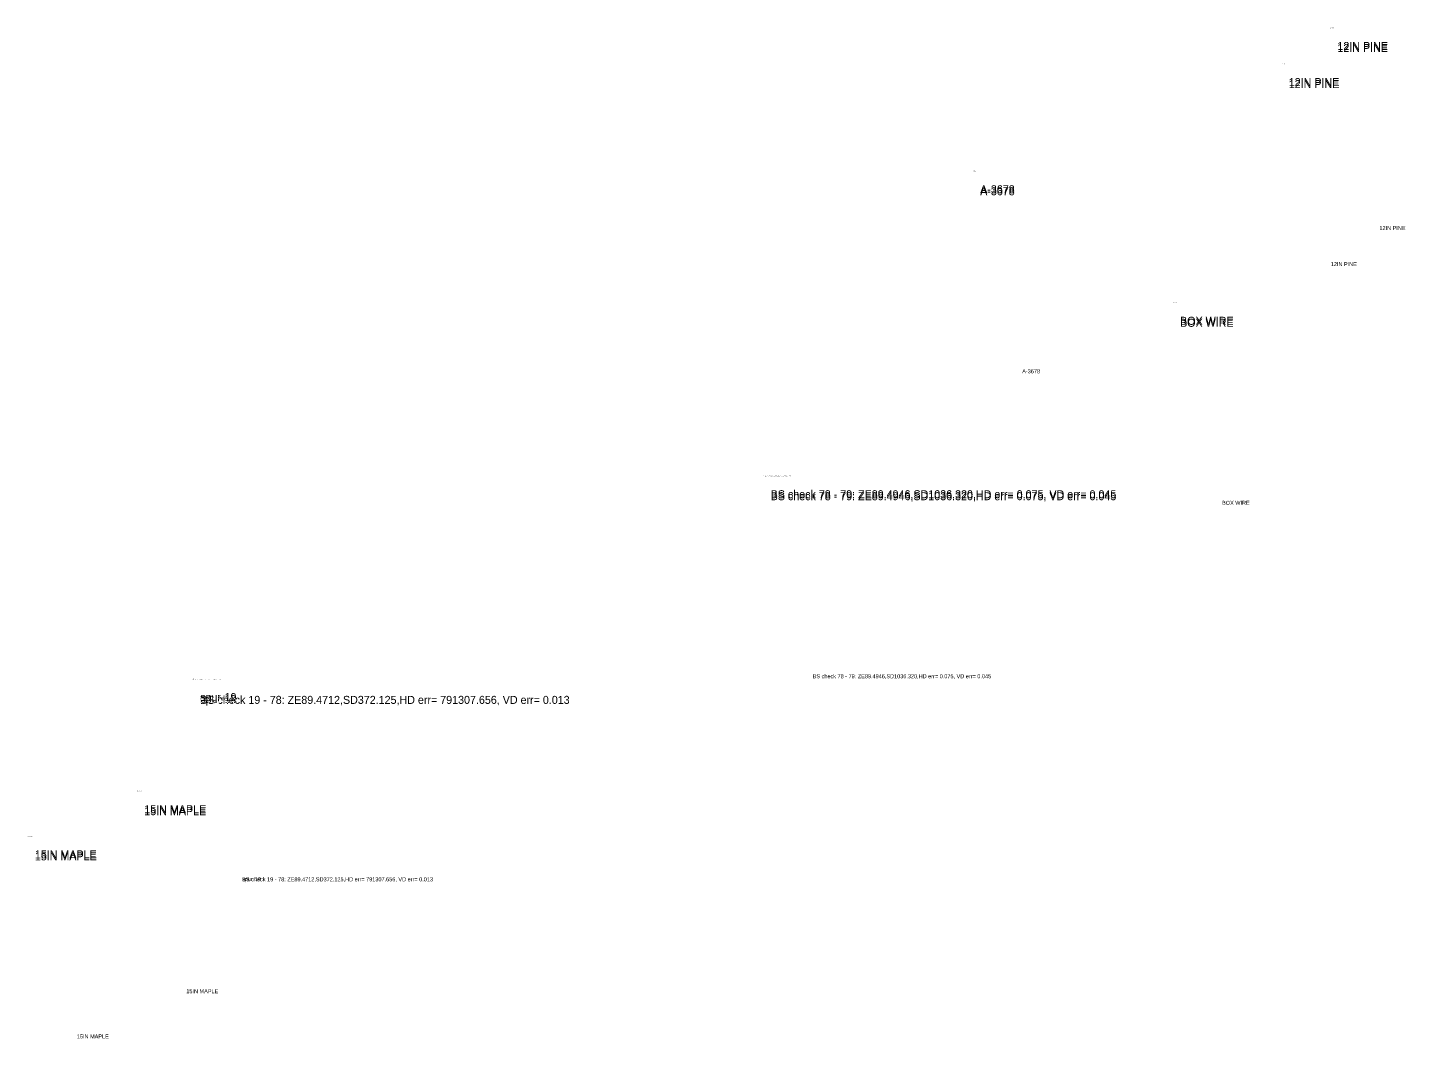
# Model space of a CAD drawing. Extents: x 5447 to 709667, y 4528 to 375472.
# Drawn here: x 704826 to 705377, y 374866 to 375270 of the extents above; entities that cross this region are included whole.
import ezdxf

# ---------------------------------------------------------------- set-up
doc = ezdxf.new("R2010")
doc.units = 0
doc.layers.add('SV_SURVEY_NOTES', color=7, linetype='Continuous')

msp = doc.modelspace()

# ---------------------------------------------------------------- texts
at = {"layer": 'SV_SURVEY_NOTES'}
for s, height, p in [('12IN PINE', 0.25, (705347.09, 375270.07)), ('12IN PINE', 3.2, (705350.04, 375261.35)), ('12IN PINE', 3.2, (705350.04, 375261.35)), ('12IN PINE', 3.2, (705350.04, 375261.35)), ('12IN PINE', 3.2, (705350.04, 375261.35)), ('12IN PINE', 3.2, (705350.04, 375261.35)), ('12IN PINE', 3.2, (705350.04, 375261.35)), ('12IN PINE', 3.2, (705350.04, 375261.35)), ('12IN PINE', 3.2, (705350.04, 375261.35)), ('12IN PINE', 3.2, (705350.04, 375260.55)), ('12IN PINE', 3.2, (705350.04, 375260.55)), ('12IN PINE', 3.2, (705350.04, 375260.55)), ('12IN PINE', 0.25, (705327.64, 375255.64)), ('12IN PINE', 3.2, (705330.59, 375246.91)), ('12IN PINE', 3.2, (705330.59, 375246.91)), ('12IN PINE', 3.2, (705330.59, 375246.91)), ('12IN PINE', 3.2, (705330.59, 375246.91)), ('12IN PINE', 3.2, (705330.59, 375246.91)), ('12IN PINE', 3.2, (705330.59, 375246.91)), ('12IN PINE', 3.2, (705330.59, 375246.91)), ('12IN PINE', 3.2, (705330.59, 375246.91)), ('12IN PINE', 3.2, (705330.59, 375246.11)), ('12IN PINE', 3.2, (705330.59, 375246.11)), ('12IN PINE', 3.2, (705330.59, 375246.11)), ('A-3678', 0.25, (705204.27, 375212.78)), ('A-3678', 0.25, (705204.27, 375212.78)), ('A-3678', 0.25, (705204.27, 375212.78)), ('A-3678', 0.25, (705204.27, 375212.78)), ('A-3678', 0.25, (705204.27, 375212.78)), ('A-3678', 0.25, (705204.27, 375212.78)), ('A-3678', 0.25, (705204.27, 375212.78)), ('A-3678', 0.25, (705204.27, 375212.78)), ('A-3678', 0.25, (705204.27, 375212.78)), ('A-3678', 3.2, (705207.22, 375204.05)), ('A-3678', 3.2, (705207.22, 375204.05)), ('A-3678', 3.2, (705207.22, 375204.05)), ('A-3678', 3.2, (705207.22, 375204.05)), ('A-3678', 3.2, (705207.22, 375204.05)), ('A-3678', 3.2, (705207.22, 375204.05)), ('A-3678', 3.2, (705207.22, 375204.05)), ('A-3678', 3.2, (705207.22, 375204.05)), ('A-3678', 3.2, (705207.22, 375204.05)), ('A-3678', 3.2, (705207.22, 375204.05)), ('A-3678', 3.2, (705207.22, 375204.05)), ('A-3678', 3.2, (705207.22, 375204.05)), ('A-3678', 3.2, (705207.22, 375204.05)), ('A-3678', 3.2, (705207.22, 375204.05)), ('A-3678', 3.2, (705207.22, 375204.05)), ('A-3678', 3.2, (705207.22, 375204.05)), ('A-3678', 3.2, (705207.22, 375204.05)), ('A-3678', 3.2, (705207.22, 375204.05)), ('A-3678', 3.2, (705207.22, 375204.05)), ('A-3678', 3.2, (705207.22, 375204.05)), ('A-3678', 3.2, (705207.22, 375204.05)), ('A-3678', 3.2, (705207.22, 375204.05)), ('A-3678', 3.2, (705207.22, 375204.05)), ('A-3678', 3.2, (705207.22, 375204.05)), ('A-3678', 3.2, (705207.22, 375204.05)), ('A-3678', 3.2, (705207.22, 375204.05)), ('A-3678', 3.2, (705207.22, 375204.05)), ('A-3678', 3.2, (705207.22, 375204.05)), ('A-3678', 3.2, (705207.22, 375204.05)), ('A-3678', 3.2, (705207.22, 375204.05)), ('A-3678', 3.2, (705207.22, 375204.05)), ('A-3678', 3.2, (705207.22, 375204.05)), ('A-3678', 3.2, (705207.22, 375204.05)), ('A-3678', 3.2, (705207.22, 375204.05)), ('A-3678', 3.2, (705207.22, 375204.05)), ('A-3678', 3.2, (705207.22, 375204.05)), ('A-3678', 3.2, (705207.22, 375204.05)), ('A-3678', 3.2, (705207.22, 375204.05)), ('A-3678', 3.2, (705207.22, 375204.05)), ('A-3678', 3.2, (705207.22, 375204.05)), ('A-3678', 3.2, (705207.22, 375204.05)), ('A-3678', 3.2, (705207.22, 375204.05)), ('A-3678', 3.2, (705207.22, 375204.05)), ('A-3678', 3.2, (705207.22, 375204.05)), ('A-3678', 3.2, (705207.22, 375204.05)), ('A-3678', 3.2, (705207.22, 375204.05)), ('A-3678', 3.2, (705207.22, 375204.05)), ('A-3678', 3.2, (705207.22, 375204.05)), ('A-3678', 3.2, (705207.22, 375204.05)), ('A-3678', 3.2, (705207.22, 375204.05)), ('A-3678', 3.2, (705207.22, 375204.05)), ('A-3678', 3.2, (705207.22, 375204.05)), ('A-3678', 3.2, (705207.22, 375204.05)), ('A-3678', 3.2, (705207.22, 375204.05)), ('A-3678', 3.2, (705207.22, 375204.05)), ('A-3678', 3.2, (705207.22, 375204.05)), ('A-3678', 3.2, (705207.22, 375204.05)), ('A-3678', 3.2, (705207.22, 375204.05)), ('A-3678', 3.2, (705207.22, 375204.05)), ('A-3678', 3.2, (705207.22, 375204.05)), ('A-3678', 3.2, (705207.22, 375204.05)), ('A-3678', 3.2, (705207.22, 375204.05)), ('A-3678', 3.2, (705207.22, 375204.05)), ('A-3678', 3.2, (705207.22, 375204.05)), ('A-3678', 3.2, (705207.22, 375204.05)), ('A-3678', 3.2, (705207.22, 375204.05)), ('A-3678', 3.2, (705207.22, 375204.05)), ('A-3678', 3.2, (705207.22, 375204.05)), ('A-3678', 3.2, (705207.22, 375204.05)), ('A-3678', 3.2, (705207.22, 375204.05)), ('A-3678', 3.2, (705207.22, 375204.05)), ('A-3678', 3.2, (705207.22, 375204.05)), ('A-3678', 3.2, (705207.22, 375203.25)), ('A-3678', 3.2, (705207.22, 375203.25)), ('A-3678', 3.2, (705207.22, 375203.25)), ('A-3678', 3.2, (705207.22, 375203.25)), ('A-3678', 3.2, (705207.22, 375203.25)), ('A-3678', 3.2, (705207.22, 375203.25)), ('A-3678', 3.2, (705207.22, 375203.25)), ('A-3678', 3.2, (705207.22, 375203.25)), ('A-3678', 3.2, (705207.22, 375203.25)), ('A-3678', 3.2, (705207.22, 375203.25)), ('A-3678', 3.2, (705207.22, 375203.25)), ('12IN PINE', 1.6, (705366.84, 375189.35)), ('12IN PINE', 1.6, (705347.39, 375174.91)), ('BOX WIRE', 0.25, (705284.18, 375160.18)), ('BOX WIRE', 3.2, (705287.13, 375151.45)), ('BOX WIRE', 3.2, (705287.13, 375151.45)), ('BOX WIRE', 3.2, (705287.13, 375151.45)), ('BOX WIRE', 3.2, (705287.13, 375151.45)), ('BOX WIRE', 3.2, (705287.13, 375151.45)), ('BOX WIRE', 3.2, (705287.13, 375151.45)), ('BOX WIRE', 3.2, (705287.13, 375151.45)), ('BOX WIRE', 3.2, (705287.13, 375151.45)), ('BOX WIRE', 3.2, (705287.13, 375150.65)), ('BOX WIRE', 3.2, (705287.13, 375150.65)), ('BOX WIRE', 3.2, (705287.13, 375150.65)), ('A-3678', 1.6, (705224.02, 375132.05)), ('A-3678', 1.6, (705224.02, 375132.05)), ('A-3678', 1.6, (705224.02, 375132.05)), ('A-3678', 1.6, (705224.02, 375132.05)), ('A-3678', 1.6, (705224.02, 375132.05)), ('A-3678', 1.6, (705224.02, 375132.05)), ('A-3678', 1.6, (705224.02, 375132.05)), ('A-3678', 1.6, (705224.02, 375132.05)), ('A-3678', 1.6, (705224.02, 375132.05)), ('BS check 78 - 79: ZE89.4946,SD1036.320,HD err= 0.075, VD err= 0.045', 0.25, (705120.5, 375090.82)), ('BS check 78 - 79: ZE89.4946,SD1036.320,HD err= 0.075, VD err= 0.045', 3.2, (705123.45, 375082.09)), ('BS check 78 - 79: ZE89.4946,SD1036.320,HD err= 0.075, VD err= 0.045', 3.2, (705123.45, 375082.09)), ('BS check 78 - 79: ZE89.4946,SD1036.320,HD err= 0.075, VD err= 0.045', 3.2, (705123.45, 375082.09)), ('BS check 78 - 79: ZE89.4946,SD1036.320,HD err= 0.075, VD err= 0.045', 3.2, (705123.45, 375082.09)), ('BS check 78 - 79: ZE89.4946,SD1036.320,HD err= 0.075, VD err= 0.045', 3.2, (705123.45, 375082.09)), ('BS check 78 - 79: ZE89.4946,SD1036.320,HD err= 0.075, VD err= 0.045', 3.2, (705123.45, 375082.09)), ('BS check 78 - 79: ZE89.4946,SD1036.320,HD err= 0.075, VD err= 0.045', 3.2, (705123.45, 375082.09)), ('BS check 78 - 79: ZE89.4946,SD1036.320,HD err= 0.075, VD err= 0.045', 3.2, (705123.45, 375082.09)), ('BS check 78 - 79: ZE89.4946,SD1036.320,HD err= 0.075, VD err= 0.045', 3.2, (705123.45, 375081.29)), ('BS check 78 - 79: ZE89.4946,SD1036.320,HD err= 0.075, VD err= 0.045', 3.2, (705123.45, 375081.29)), ('BS check 78 - 79: ZE89.4946,SD1036.320,HD err= 0.075, VD err= 0.045', 3.2, (705123.45, 375081.29)), ('BOX WIRE', 1.6, (705303.93, 375079.45)), ('spur-19', 0.25, (704892.42, 375009.69)), ('spur-19', 0.25, (704892.42, 375009.69)), ('spur-19', 0.25, (704892.42, 375009.69)), ('spur-19', 0.25, (704892.42, 375009.69)), ('spur-19', 0.25, (704892.42, 375009.69)), ('BS check 19 - 78: ZE89.4712,SD372.125,HD err= 791307.656, VD err= 0.013', 0.25, (704892.42, 375009.34)), ('BS check 19 - 78: ZE89.4712,SD372.125,HD err= 791307.656, VD err= 0.013', 0.25, (704892.42, 375009.34)), ('BS check 19 - 78: ZE89.4712,SD372.125,HD err= 791307.656, VD err= 0.013', 0.25, (704892.42, 375009.34)), ('BS check 19 - 78: ZE89.4712,SD372.125,HD err= 791307.656, VD err= 0.013', 0.25, (704892.42, 375009.34)), ('BS check 19 - 78: ZE89.4712,SD372.125,HD err= 791307.656, VD err= 0.013', 0.25, (704892.42, 375009.34)), ('BS check 78 - 79: ZE89.4946,SD1036.320,HD err= 0.075, VD err= 0.045', 1.6, (705140.25, 375010.09)), ('spur-19', 3.2, (704895.37, 375000.96)), ('spur-19', 3.2, (704895.37, 375000.96)), ('spur-19', 3.2, (704895.37, 375000.96)), ('spur-19', 3.2, (704895.37, 375000.96)), ('spur-19', 3.2, (704895.37, 375000.96)), ('spur-19', 3.2, (704895.37, 375000.96)), ('spur-19', 3.2, (704895.37, 375000.96)), ('spur-19', 3.2, (704895.37, 375000.96)), ('spur-19', 3.2, (704895.37, 375000.96)), ('spur-19', 3.2, (704895.37, 375000.96)), ('spur-19', 3.2, (704895.37, 375000.96)), ('spur-19', 3.2, (704895.37, 375000.96)), ('spur-19', 3.2, (704895.37, 375000.96)), ('spur-19', 3.2, (704895.37, 375000.96)), ('spur-19', 3.2, (704895.37, 375000.96)), ('spur-19', 3.2, (704895.37, 375000.96)), ('spur-19', 3.2, (704895.37, 375000.96)), ('spur-19', 3.2, (704895.37, 375000.96)), ('spur-19', 3.2, (704895.37, 375000.96)), ('spur-19', 3.2, (704895.37, 375000.96)), ('spur-19', 3.2, (704895.37, 375000.96)), ('spur-19', 3.2, (704895.37, 375000.96)), ('spur-19', 3.2, (704895.37, 375000.96)), ('spur-19', 3.2, (704895.37, 375000.96)), ('spur-19', 3.2, (704895.37, 375000.96)), ('spur-19', 3.2, (704895.37, 375000.96)), ('spur-19', 3.2, (704895.37, 375000.96)), ('spur-19', 3.2, (704895.37, 375000.96)), ('spur-19', 3.2, (704895.37, 375000.96)), ('spur-19', 3.2, (704895.37, 375000.96)), ('spur-19', 3.2, (704895.37, 375000.96)), ('spur-19', 3.2, (704895.37, 375000.96)), ('spur-19', 3.2, (704895.37, 375000.96)), ('spur-19', 3.2, (704895.37, 375000.96)), ('spur-19', 3.2, (704895.37, 375000.96)), ('spur-19', 3.2, (704895.37, 375000.96)), ('spur-19', 3.2, (704895.37, 375000.96)), ('spur-19', 3.2, (704895.37, 375000.96)), ('spur-19', 3.2, (704895.37, 375000.96)), ('spur-19', 3.2, (704895.37, 375000.96)), ('spur-19', 3.2, (704895.37, 375000.16)), ('spur-19', 3.2, (704895.37, 375000.16)), ('spur-19', 3.2, (704895.37, 375000.16)), ('spur-19', 3.2, (704895.37, 375000.16)), ('spur-19', 3.2, (704895.37, 375000.16)), ('spur-19', 3.2, (704895.37, 375000.16)), ('spur-19', 3.2, (704895.37, 375000.16)), ('spur-19', 3.2, (704895.37, 375000.16)), ('spur-19', 3.2, (704895.37, 375000.16)), ('BS check 19 - 78: ZE89.4712,SD372.125,HD err= 791307.656, VD err= 0.013', 3.2, (704895.37, 375000.65)), ('BS check 19 - 78: ZE89.4712,SD372.125,HD err= 791307.656, VD err= 0.013', 3.2, (704895.37, 375000.65)), ('BS check 19 - 78: ZE89.4712,SD372.125,HD err= 791307.656, VD err= 0.013', 3.2, (704895.37, 375000.65)), ('BS check 19 - 78: ZE89.4712,SD372.125,HD err= 791307.656, VD err= 0.013', 3.2, (704895.37, 375000.65)), ('BS check 19 - 78: ZE89.4712,SD372.125,HD err= 791307.656, VD err= 0.013', 3.2, (704895.37, 375000.65)), ('BS check 19 - 78: ZE89.4712,SD372.125,HD err= 791307.656, VD err= 0.013', 3.2, (704895.37, 375000.65)), ('BS check 19 - 78: ZE89.4712,SD372.125,HD err= 791307.656, VD err= 0.013', 3.2, (704895.37, 375000.65)), ('BS check 19 - 78: ZE89.4712,SD372.125,HD err= 791307.656, VD err= 0.013', 3.2, (704895.37, 375000.65)), ('BS check 19 - 78: ZE89.4712,SD372.125,HD err= 791307.656, VD err= 0.013', 3.2, (704895.37, 375000.65)), ('BS check 19 - 78: ZE89.4712,SD372.125,HD err= 791307.656, VD err= 0.013', 3.2, (704895.37, 375000.65)), ('BS check 19 - 78: ZE89.4712,SD372.125,HD err= 791307.656, VD err= 0.013', 3.2, (704895.37, 375000.65)), ('BS check 19 - 78: ZE89.4712,SD372.125,HD err= 791307.656, VD err= 0.013', 3.2, (704895.37, 375000.65)), ('BS check 19 - 78: ZE89.4712,SD372.125,HD err= 791307.656, VD err= 0.013', 3.2, (704895.37, 375000.65)), ('BS check 19 - 78: ZE89.4712,SD372.125,HD err= 791307.656, VD err= 0.013', 3.2, (704895.37, 375000.65)), ('BS check 19 - 78: ZE89.4712,SD372.125,HD err= 791307.656, VD err= 0.013', 3.2, (704895.37, 375000.65)), ('BS check 19 - 78: ZE89.4712,SD372.125,HD err= 791307.656, VD err= 0.013', 3.2, (704895.37, 375000.65)), ('BS check 19 - 78: ZE89.4712,SD372.125,HD err= 791307.656, VD err= 0.013', 3.2, (704895.37, 375000.65)), ('BS check 19 - 78: ZE89.4712,SD372.125,HD err= 791307.656, VD err= 0.013', 3.2, (704895.37, 375000.65)), ('BS check 19 - 78: ZE89.4712,SD372.125,HD err= 791307.656, VD err= 0.013', 3.2, (704895.37, 375000.65)), ('BS check 19 - 78: ZE89.4712,SD372.125,HD err= 791307.656, VD err= 0.013', 3.2, (704895.37, 375000.65)), ('BS check 19 - 78: ZE89.4712,SD372.125,HD err= 791307.656, VD err= 0.013', 3.2, (704895.37, 375000.65)), ('BS check 19 - 78: ZE89.4712,SD372.125,HD err= 791307.656, VD err= 0.013', 3.2, (704895.37, 375000.65)), ('BS check 19 - 78: ZE89.4712,SD372.125,HD err= 791307.656, VD err= 0.013', 3.2, (704895.37, 375000.65)), ('BS check 19 - 78: ZE89.4712,SD372.125,HD err= 791307.656, VD err= 0.013', 3.2, (704895.37, 375000.65)), ('BS check 19 - 78: ZE89.4712,SD372.125,HD err= 791307.656, VD err= 0.013', 3.2, (704895.37, 375000.65)), ('BS check 19 - 78: ZE89.4712,SD372.125,HD err= 791307.656, VD err= 0.013', 3.2, (704895.37, 375000.65)), ('BS check 19 - 78: ZE89.4712,SD372.125,HD err= 791307.656, VD err= 0.013', 3.2, (704895.37, 375000.65)), ('BS check 19 - 78: ZE89.4712,SD372.125,HD err= 791307.656, VD err= 0.013', 3.2, (704895.37, 375000.65)), ('BS check 19 - 78: ZE89.4712,SD372.125,HD err= 791307.656, VD err= 0.013', 3.2, (704895.37, 375000.65)), ('BS check 19 - 78: ZE89.4712,SD372.125,HD err= 791307.656, VD err= 0.013', 3.2, (704895.37, 375000.65)), ('BS check 19 - 78: ZE89.4712,SD372.125,HD err= 791307.656, VD err= 0.013', 3.2, (704895.37, 375000.65)), ('BS check 19 - 78: ZE89.4712,SD372.125,HD err= 791307.656, VD err= 0.013', 3.2, (704895.37, 375000.65)), ('BS check 19 - 78: ZE89.4712,SD372.125,HD err= 791307.656, VD err= 0.013', 3.2, (704895.37, 375000.65)), ('BS check 19 - 78: ZE89.4712,SD372.125,HD err= 791307.656, VD err= 0.013', 3.2, (704895.37, 375000.65)), ('BS check 19 - 78: ZE89.4712,SD372.125,HD err= 791307.656, VD err= 0.013', 3.2, (704895.37, 375000.65)), ('BS check 19 - 78: ZE89.4712,SD372.125,HD err= 791307.656, VD err= 0.013', 3.2, (704895.37, 375000.65)), ('BS check 19 - 78: ZE89.4712,SD372.125,HD err= 791307.656, VD err= 0.013', 3.2, (704895.37, 375000.65)), ('BS check 19 - 78: ZE89.4712,SD372.125,HD err= 791307.656, VD err= 0.013', 3.2, (704895.37, 375000.65)), ('BS check 19 - 78: ZE89.4712,SD372.125,HD err= 791307.656, VD err= 0.013', 3.2, (704895.37, 375000.65)), ('BS check 19 - 78: ZE89.4712,SD372.125,HD err= 791307.656, VD err= 0.013', 3.2, (704895.37, 375000.65)), ('BS check 19 - 78: ZE89.4712,SD372.125,HD err= 791307.656, VD err= 0.013', 3.2, (704895.37, 374999.85)), ('BS check 19 - 78: ZE89.4712,SD372.125,HD err= 791307.656, VD err= 0.013', 3.2, (704895.37, 374999.85)), ('BS check 19 - 78: ZE89.4712,SD372.125,HD err= 791307.656, VD err= 0.013', 3.2, (704895.37, 374999.85)), ('BS check 19 - 78: ZE89.4712,SD372.125,HD err= 791307.656, VD err= 0.013', 3.2, (704895.37, 374999.85)), ('BS check 19 - 78: ZE89.4712,SD372.125,HD err= 791307.656, VD err= 0.013', 3.2, (704895.37, 374999.85)), ('BS check 19 - 78: ZE89.4712,SD372.125,HD err= 791307.656, VD err= 0.013', 3.2, (704895.37, 374999.85)), ('BS check 19 - 78: ZE89.4712,SD372.125,HD err= 791307.656, VD err= 0.013', 3.2, (704895.37, 374999.85)), ('BS check 19 - 78: ZE89.4712,SD372.125,HD err= 791307.656, VD err= 0.013', 3.2, (704895.37, 374999.85)), ('BS check 19 - 78: ZE89.4712,SD372.125,HD err= 791307.656, VD err= 0.013', 3.2, (704895.37, 374999.85)), ('15IN MAPLE', 0.25, (704870.09, 374964.86)), ('15IN MAPLE', 3.2, (704873.04, 374956.13)), ('15IN MAPLE', 3.2, (704873.04, 374956.13)), ('15IN MAPLE', 3.2, (704873.04, 374956.13)), ('15IN MAPLE', 3.2, (704873.04, 374956.13)), ('15IN MAPLE', 3.2, (704873.04, 374956.13)), ('15IN MAPLE', 3.2, (704873.04, 374956.13)), ('15IN MAPLE', 3.2, (704873.04, 374956.13)), ('15IN MAPLE', 3.2, (704873.04, 374956.13)), ('15IN MAPLE', 3.2, (704873.04, 374955.33)), ('15IN MAPLE', 3.2, (704873.04, 374955.33)), ('15IN MAPLE', 3.2, (704873.04, 374955.33)), ('15IN MAPLE', 0.25, (704826.32, 374946.79)), ('15IN MAPLE', 3.2, (704829.27, 374938.06)), ('15IN MAPLE', 3.2, (704829.27, 374938.06)), ('15IN MAPLE', 3.2, (704829.27, 374938.06)), ('15IN MAPLE', 3.2, (704829.27, 374938.06)), ('15IN MAPLE', 3.2, (704829.27, 374938.06)), ('15IN MAPLE', 3.2, (704829.27, 374938.06)), ('15IN MAPLE', 3.2, (704829.27, 374938.06)), ('15IN MAPLE', 3.2, (704829.27, 374938.06)), ('15IN MAPLE', 3.2, (704829.27, 374937.26)), ('15IN MAPLE', 3.2, (704829.27, 374937.26)), ('15IN MAPLE', 3.2, (704829.27, 374937.26)), ('spur-19', 1.6, (704912.17, 374928.96)), ('spur-19', 1.6, (704912.17, 374928.96)), ('spur-19', 1.6, (704912.17, 374928.96)), ('spur-19', 1.6, (704912.17, 374928.96)), ('spur-19', 1.6, (704912.17, 374928.96)), ('BS check 19 - 78: ZE89.4712,SD372.125,HD err= 791307.656, VD err= 0.013', 1.6, (704912.17, 374928.89)), ('BS check 19 - 78: ZE89.4712,SD372.125,HD err= 791307.656, VD err= 0.013', 1.6, (704912.17, 374928.89)), ('BS check 19 - 78: ZE89.4712,SD372.125,HD err= 791307.656, VD err= 0.013', 1.6, (704912.17, 374928.89)), ('BS check 19 - 78: ZE89.4712,SD372.125,HD err= 791307.656, VD err= 0.013', 1.6, (704912.17, 374928.89)), ('BS check 19 - 78: ZE89.4712,SD372.125,HD err= 791307.656, VD err= 0.013', 1.6, (704912.17, 374928.89)), ('15IN MAPLE', 1.6, (704889.83, 374884.13)), ('15IN MAPLE', 1.6, (704846.07, 374866.06))]:
    msp.add_text(s, height=height, dxfattribs=at).set_placement(p)

doc.saveas('drawing.dxf')
